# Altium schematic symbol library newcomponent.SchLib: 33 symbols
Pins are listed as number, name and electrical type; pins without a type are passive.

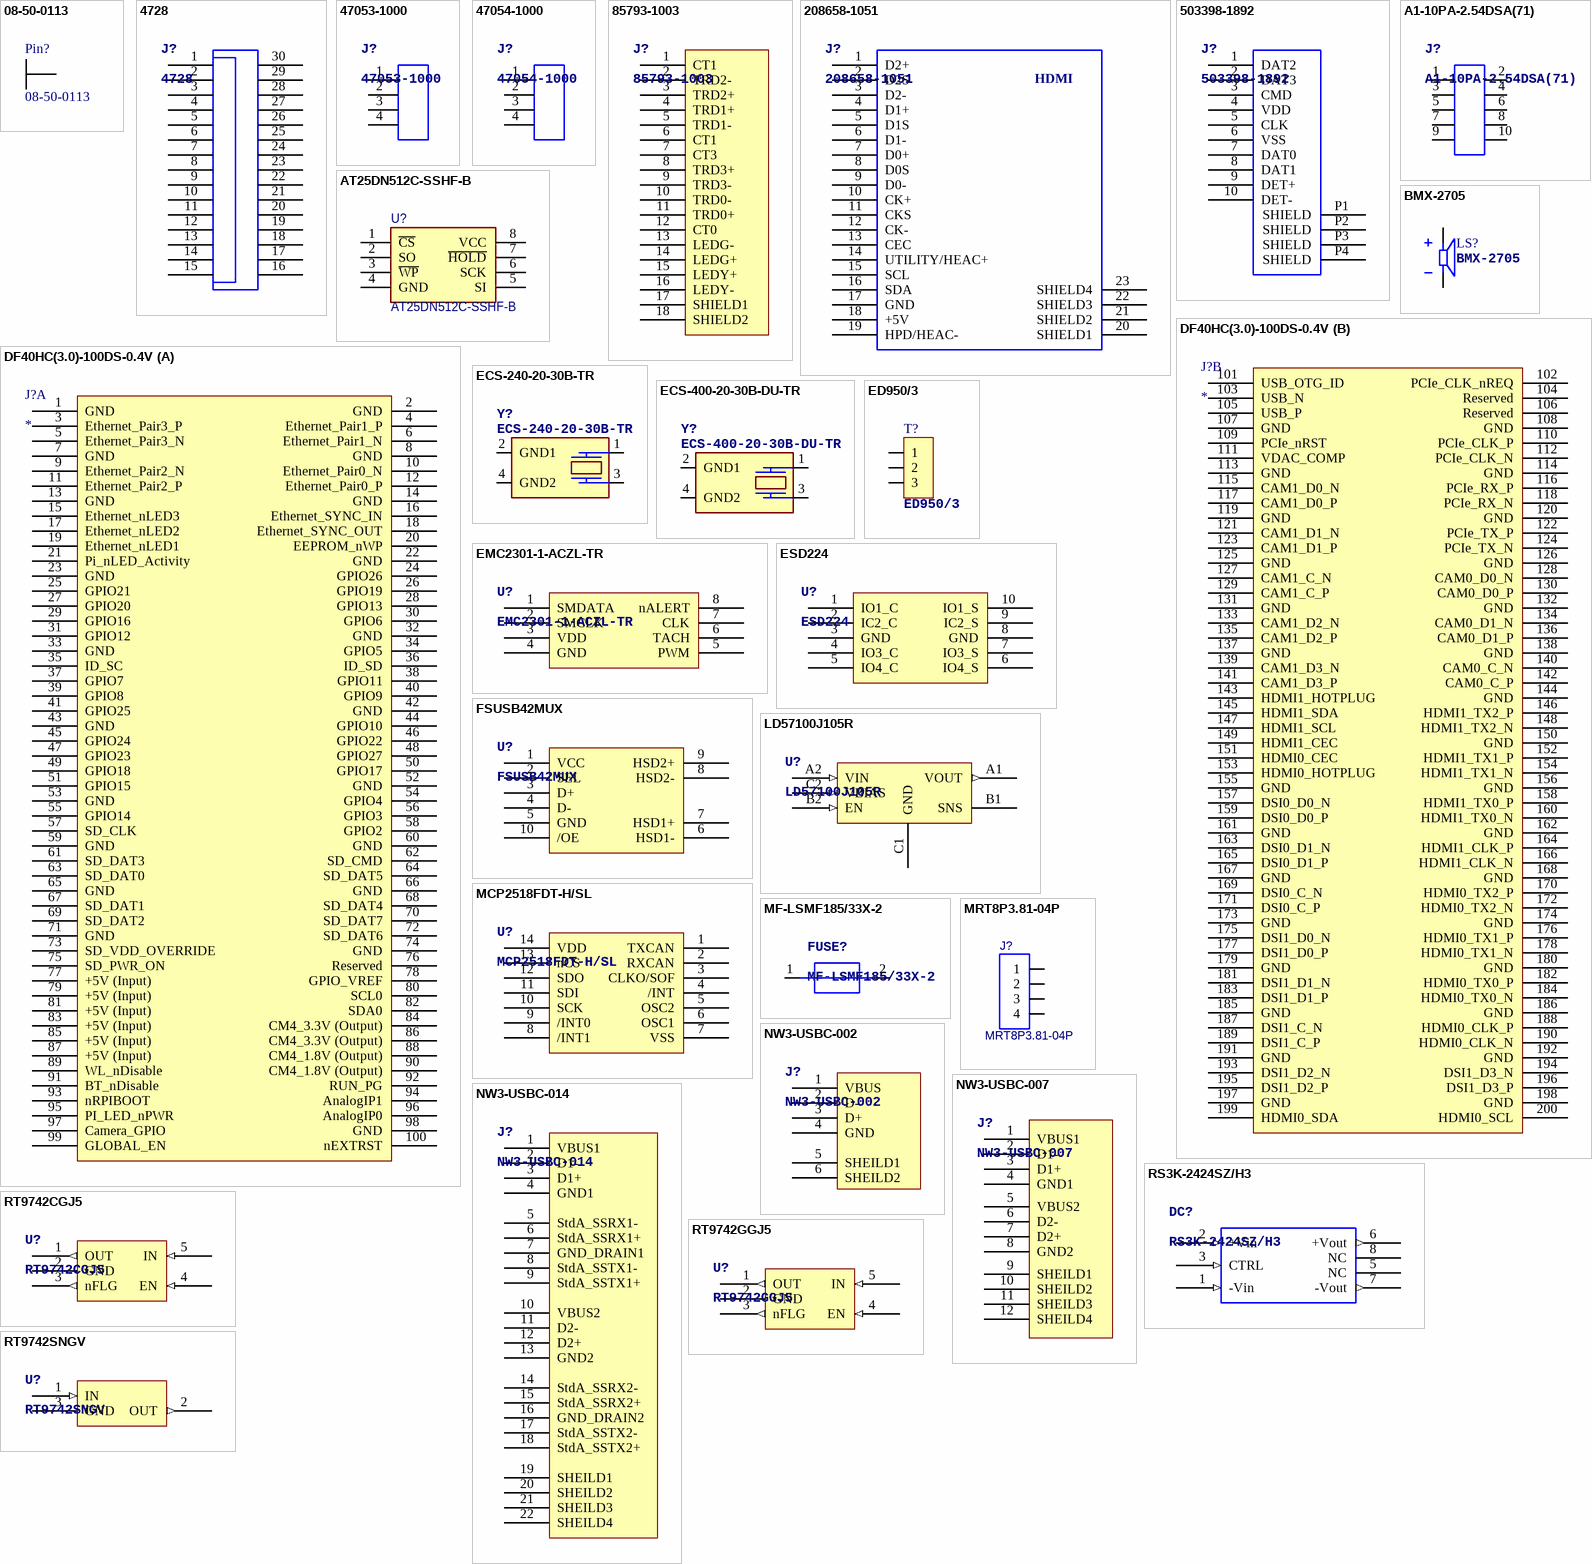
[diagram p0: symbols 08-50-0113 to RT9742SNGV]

## 08-50-0113
designator Pin?  (mechanical)
Headers & Wire Housings KK TERM 22-30G / (Use with 47054-1000); Maker: Molex

## 4728
designator J?
Raspberry Pi Accessories Replacement CSI/DSI Connector for Raspberry Pi - Repair Part; Maker: Adafruit
pins: 1, 2, 3, 4, 5, 6, 7, 8, 9, 10, 11, 12, 13, 14, 15, 16, 17, 18, 19, 20, 21, 22, 23, 24, 25, 26, 27, 28, 29, 30

## 47053-1000
designator J?
KK 254 Vertical Header, with Friction Lock, 4 Circuits, PC Tail Length 3.50mm, Bag; Maker: Molex; Plating: 151ConductorMaterial; Number of Contacts: 4; Gender: Male; Current Rating: 4A; Voltage Rating: 250V; Pitch: 2.54mm; Glow Wire Compliant: Non-compliant
pins: 1, 2, 3, 4

## 47054-1000
designator J?
Headers & Wire Housings KK .100" HSG 04P; PartNo.: 47053-1000; Maker: Molex
pins: 1, 2, 3, 4

## 85793-1003
designator J?
Gigabit Ethernet Connectors 8/8 RA Magnetic Jack Grn/Orange/Grn LED; Maker: Molex
pins: 1 CT1, 2 TRD2-, 3 TRD2+, 4 TRD1+, 5 TRD1-, 6 CT1, 7 CT3, 8 TRD3+, 9 TRD3-, 10 TRD0-, 11 TRD0+, 12 CT0, 13 LEDG-, 14 LEDG+, 15 LEDY+, 16 LEDY-, 17 SHIELD1, 18 SHIELD2

## 208658-1051
designator J?
HDMI 2.1 Receptacle Connector 19 Position Surface Mount, Right Angle; Through Hole; PartNo.: 2086581051; Maker: Molex
pins: 1 D2+, 2 D2S, 3 D2-, 4 D1+, 5 D1S, 6 D1-, 7 D0+, 8 D0S, 9 D0-, 10 CK+, 11 CKS, 12 CK-, 13 CEC, 14 UTILITY/HEAC+, 15 SCL, 16 SDA, 17 GND, 18 +5V, 19 HPD/HEAC-, 20 SHIELD1, 21 SHIELD2, 22 SHIELD3, 23 SHIELD4

## 503398-1892
designator J?
Memory Card Connectors MICRO SD PUSH/PUSH NORMAL 1.28MM 8C; Maker: Molex
pins: 1 DAT2, 2 DAT3, 3 CMD, 4 VDD, 5 CLK, 6 VSS, 7 DAT0, 8 DAT1, 9 DET+, 10 DET-, P1 SHIELD, P2 SHIELD, P3 SHIELD, P4 SHIELD

## A1-10PA-2.54DSA(71)
designator J?
Headers & Wire Housings 10P M PIN HEADER DR STRAIGHT TYPE GOLD; Maker: Hirose
pins: 1, 2, 3, 4, 5, 6, 7, 8, 9, 10

## AT25DN512C-SSHF-B
designator U?
NOR Flash 512 Kbit, 3.0V (2.3V to 3.6V), -40C to 85C, SOIC-N 150mil (Tube), Single, Dual SPI NOR flash; Maker: Renesas / Dialog
footprint SO-08-EIAJ
pins: 1 ~{CS}, 2 SO, 3 ~{WP}, 4 GND, 5 SI, 6 SCK, 7 ~{HOLD}, 8 VCC

## BMX-2705
designator LS?
9 mm, 5 Vdc, 90 dB, SMD Passive, Magnetic Audio Indicator Buzzer; Maker: KANGSEO EST
pins: N, P

## DF40HC(3.0)-100DS-0.4V
designator J?
Board to Board & Mezzanine Connectors 100P 2R 3MM RECPT SMT VERT 0.4MM PITCH; PartNo.: DF40HC(3.0)-100DS-0.4V; Maker: Hirose
part A pins: 1 GND, 2 GND, 3 Ethernet_Pair3_P, 4 Ethernet_Pair1_P, 5 Ethernet_Pair3_N, 6 Ethernet_Pair1_N, 7 GND, 8 GND, 9 Ethernet_Pair2_N, 10 Ethernet_Pair0_N, 11 Ethernet_Pair2_P, 12 Ethernet_Pair0_P, 13 GND, 14 GND, 15 Ethernet_nLED3, 16 Ethernet_SYNC_IN, 17 Ethernet_nLED2, 18 Ethernet_SYNC_OUT, 19 Ethernet_nLED1, 20 EEPROM_nWP, 21 Pi_nLED_Activity, 22 GND, 23 GND, 24 GPIO26, 25 GPIO21, 26 GPIO19, 27 GPIO20, 28 GPIO13, 29 GPIO16, 30 GPIO6, 31 GPIO12, 32 GND, 33 GND, 34 GPIO5, 35 ID_SC, 36 ID_SD, 37 GPIO7, 38 GPIO11, 39 GPIO8, 40 GPIO9, 41 GPIO25, 42 GND, 43 GND, 44 GPIO10, 45 GPIO24, 46 GPIO22, 47 GPIO23, 48 GPIO27, 49 GPIO18, 50 GPIO17, 51 GPIO15, 52 GND, 53 GND, 54 GPIO4, 55 GPIO14, 56 GPIO3, 57 SD_CLK, 58 GPIO2, 59 GND, 60 GND, 61 SD_DAT3, 62 SD_CMD, 63 SD_DAT0, 64 SD_DAT5, 65 GND, 66 GND, 67 SD_DAT1, 68 SD_DAT4, 69 SD_DAT2, 70 SD_DAT7, 71 GND, 72 SD_DAT6, 73 SD_VDD_OVERRIDE, 74 GND, 75 SD_PWR_ON, 76 Reserved, 77 +5V (Input), 78 GPIO_VREF, 79 +5V (Input), 80 SCL0, 81 +5V (Input), 82 SDA0, 83 +5V (Input), 84 CM4_3.3V (Output), 85 +5V (Input), 86 CM4_3.3V (Output), 87 +5V (Input), 88 CM4_1.8V (Output), 89 WL_nDisable, 90 CM4_1.8V (Output), 91 BT_nDisable, 92 RUN_PG, 93 nRPIBOOT, 94 AnalogIP1, 95 PI_LED_nPWR, 96 AnalogIP0, 97 Camera_GPIO, 98 GND, 99 GLOBAL_EN, 100 nEXTRST
part B pins: 101 USB_OTG_ID, 102 PCIe_CLK_nREQ, 103 USB_N, 104 Reserved, 105 USB_P, 106 Reserved, 107 GND, 108 GND, 109 PCIe_nRST, 110 PCIe_CLK_P, 111 VDAC_COMP, 112 PCIe_CLK_N, 113 GND, 114 GND, 115 CAM1_D0_N, 116 PCIe_RX_P, 117 CAM1_D0_P, 118 PCIe_RX_N, 119 GND, 120 GND, 121 CAM1_D1_N, 122 PCIe_TX_P, 123 CAM1_D1_P, 124 PCIe_TX_N, 125 GND, 126 GND, 127 CAM1_C_N, 128 CAM0_D0_N, 129 CAM1_C_P, 130 CAM0_D0_P, 131 GND, 132 GND, 133 CAM1_D2_N, 134 CAM0_D1_N, 135 CAM1_D2_P, 136 CAM0_D1_P, 137 GND, 138 GND, 139 CAM1_D3_N, 140 CAM0_C_N, 141 CAM1_D3_P, 142 CAM0_C_P, 143 HDMI1_HOTPLUG, 144 GND, 145 HDMI1_SDA, 146 HDMI1_TX2_P, 147 HDMI1_SCL, 148 HDMI1_TX2_N, 149 HDMI1_CEC, 150 GND, 151 HDMI0_CEC, 152 HDMI1_TX1_P, 153 HDMI0_HOTPLUG, 154 HDMI1_TX1_N, 155 GND, 156 GND, 157 DSI0_D0_N, 158 HDMI1_TX0_P, 159 DSI0_D0_P, 160 HDMI1_TX0_N, 161 GND, 162 GND, 163 DSI0_D1_N, 164 HDMI1_CLK_P, 165 DSI0_D1_P, 166 HDMI1_CLK_N, 167 GND, 168 GND, 169 DSI0_C_N, 170 HDMI0_TX2_P, 171 DSI0_C_P, 172 HDMI0_TX2_N, 173 GND, 174 GND, 175 DSI1_D0_N, 176 HDMI0_TX1_P, 177 DSI1_D0_P, 178 HDMI0_TX1_N, 179 GND, 180 GND, 181 DSI1_D1_N, 182 HDMI0_TX0_P, 183 DSI1_D1_P, 184 HDMI0_TX0_N, 185 GND, 186 GND, 187 DSI1_C_N, 188 HDMI0_CLK_P, 189 DSI1_C_P, 190 HDMI0_CLK_N, 191 GND, 192 GND, 193 DSI1_D2_N, 194 DSI1_D3_N, 195 DSI1_D2_P, 196 DSI1_D3_P, 197 GND, 198 GND, 199 HDMI0_SDA, 200 HDMI0_SCL

## ECS-240-20-30B-TR
designator Y?
Crystal 24MHz ±30ppm (Tol) ±50ppm (Stability) 20pF FUND 80Ohm 4-Pin Mini-SMD T/R; Maker: ECS
footprint xtal-ECS-120-20-30B-TR
pins: 1 IN/OUT, 2 GND1, 3 OUT/IN, 4 GND2

## ECS-400-20-30B-DU-TR
designator Y?
Crystal 40MHz ±30ppm (Tol) ±100ppm (Stability) 20pF FUND 100Ohm 4-Pin Mini-SMD T/R; Maker: ECS
footprint xtal-ECS-120-20-30B-TR
pins: 1 IN/OUT, 2 GND1, 3 OUT/IN, 4 GND2

## ED950/3
designator T?
TERM BLOCK PLUG 3POS STR 5MM; Maker: OnShore
pins: 1, 2, 3
2 alternate drawings of the same symbol

## EMC2301-1-ACZL-TR
designator U?
Board Mount Temperature Sensors Single RPB-Based PWM Fan Speed CNTRL; Maker: Microchip
pins: 1 SMDATA, 2 SMCLK, 3 VDD, 4 GND, 5 PWM, 6 TACH, 7 CLK, 8 nALERT

## ESD224
designator U?
ESD Suppressors / TVS Diodes Quad 0.5-pF, 3.6-V, 12-kV ESD protection diode for USB &amp; HDMI 10-USON -40 to 125; Maker: TI
pins: 1 IO1_C, 2 IC2_C, 3 GND, 4 IO3_C, 5 IO4_C, 6 IO4_S, 7 IO3_S, 8 GND, 9 IC2_S, 10 IO1_S

## FSUSB42MUX
designator U?
USB Switch ICs Low Power, Two-Port USB 2.0 (480Mbps); Maker: ONSEMI
pins: 1 VCC, 2 SEL, 3 D+, 4 D-, 5 GND, 6 HSD1-, 7 HSD1+, 8 HSD2-, 9 HSD2+, 10 /OE

## LD57100J105R
designator U?
LDO Voltage Regulators 3V~5.5V to 1.05V 1A ultra low-dropout LDO bias; Maker: STMicroelectronics
pins: A1 VOUT (out), A2 VIN (in), B1 SNS, B2 EN (in), C1 GND, C2 VBIAS (in)

## MCP2518FDT-H/SL
designator U?
CAN Interface IC Stand-alone Low Power CAN FD Controller s/SPI Interface Grade 0; Maker: MIcrochip
pins: 1 TXCAN, 2 RXCAN, 3 CLKO/SOF, 4 /INT, 5 OSC2, 6 OSC1, 7 VSS, 8 /INT1, 9 /INT0, 10 SCK, 11 SDI, 12 SDO, 13 nCS, 14 VDD

## MF-LSMF185/33X-2
designator FUSE?
Resettable Fuses - PPTC PTC RESETTABLE 1.85A 33V SMD 2920; Maker: Bourns
pins: 1, 2

## MRT8P3.81-04P
designator J?
TERM BLOCK PLUG 4POS STR 3.81mm(MRT9P3.81SQ-04P need); Maker: STELVIO
pins: 1, 2, 3, 4

## NW3-USBC-002
designator J?
USB 2.0 A/F Connector, Right angle; Maker: NW3
pins: 1 VBUS, 2 D-, 3 D+, 4 GND, 5 SHEILD1, 6 SHEILD2

## NW3-USBC-007
designator J?
USB 2.0 A/F 2 stack Connector, Right angle; Maker: NW3
pins: 1 VBUS1, 2 D1-, 3 D1+, 4 GND1, 5 VBUS2, 6 D2-, 7 D2+, 8 GND2, 9 SHEILD1, 10 SHEILD2, 11 SHEILD3, 12 SHEILD4

## NW3-USBC-014
designator J?
USB 3.0 A/F 2 stack Connector, Right angle; Maker: NW3
pins: 1 VBUS1, 2 D1-, 3 D1+, 4 GND1, 5 StdA_SSRX1-, 6 StdA_SSRX1+, 7 GND_DRAIN1, 8 StdA_SSTX1-, 9 StdA_SSTX1+, 10 VBUS2, 11 D2-, 12 D2+, 13 GND2, 14 StdA_SSRX2-, 15 StdA_SSRX2+, 16 GND_DRAIN2, 17 StdA_SSTX2-, 18 StdA_SSTX2+, 19 SHEILD1, 20 SHEILD2, 21 SHEILD3, 22 SHEILD4

## RS3K-2424SZ/H3
designator DC?
Isolated DC/DC Converters - Through Hole 3W 9-36Vin 24Vout 125mA; Maker: RECOM
pins: 1 -Vin (in), 2 +Vin (in), 3 CTRL (in), 5 NC, 6 +Vout (out), 7 -Vout (out), 8 NC

## RT9742CGJ5
designator U?
Power Switch ICs - Power Distribution 70mohm, 2A High-Side Power Switches with flag; Maker: Richtek
pins: 1 OUT (out), 2 GND, 3 nFLG (out), 4 EN (in), 5 IN (in)

## RT9742GGJ5
designator U?
Power Switch ICs - Power Distribution 70mohm, 1A High-Side Power Switches with flag; Maker: Richtek
pins: 1 OUT (out), 2 GND, 3 nFLG (out), 4 EN (in), 5 IN (in)

## RT9742SNGV
designator U?
Power Switch ICs - Power Distribution 70mohm, 0.5A High-Side Power Switches, Current Limiter; Maker: Richtek
pins: 1 IN (in), 2 OUT (out), 3 GND

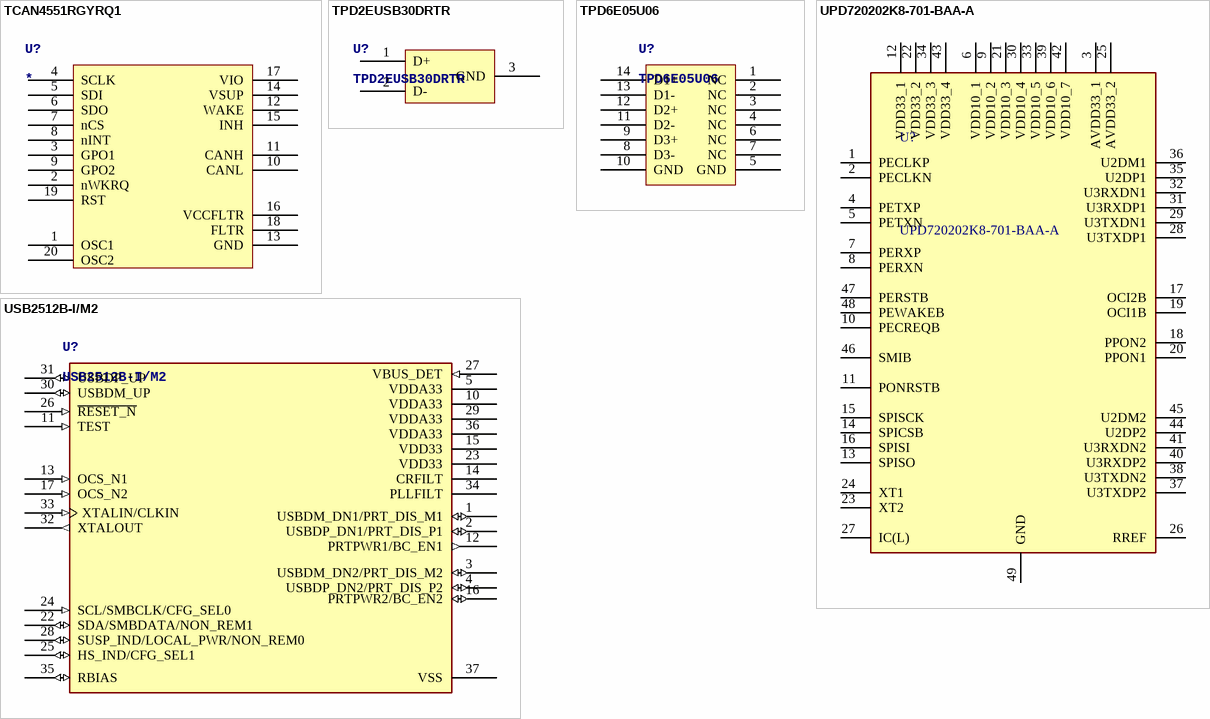
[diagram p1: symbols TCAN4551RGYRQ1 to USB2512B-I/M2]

## TCAN4551RGYRQ1
designator U?
CAN Interface IC Automotive control area network flexible data rate (CAN FD) controller with integrated transceiver 20-VQFN -40 to 125; PartNo.: TCAN4551RGYRQ1; Maker: TI
pins: 1 OSC1, 2 nWKRQ, 3 GPO1, 4 SCLK, 5 SDI, 6 SDO, 7 nCS, 8 nINT, 9 GPO2, 10 CANL, 11 CANH, 12 WAKE, 13 GND, 14 VSUP, 15 INH, 16 VCCFLTR, 17 VIO, 18 FLTR, 19 RST, 20 OSC2

## TPD2EUSB30DRTR
designator U?
ESD Suppressors / TVS Diodes 2Ch ESD Solution; PartNo.: Package; Maker: TI
pins: 1 D+, 2 D-, 3 GND

## TPD6E05U06
designator U?
ESD Suppressors / TVS Diodes 6-CH lo cap IEC ESD protect diodes; Maker: TI
pins: 1 NC, 2 NC, 3 NC, 4 NC, 5 GND, 6 NC, 7 NC, 8 D3-, 9 D3+, 10 GND, 11 D2-, 12 D2+, 13 D1-, 14 D1+

## UPD720202K8-701-BAA-A
designator U?
PD720202 is a USB host controller LSI compatible with the USB 3.0 and xHCI (eXtensible Host Controller Interface) 1.0 specifications. The system bus is compatible with the PCIe Gen2 specification. The controller provides two USB ports with LS (Low-Speed) / FS (Full-Speed) / HS (High-Speed) / SS (SuperSpeed) support.PD720202 comes in a 48-pin QFN package and has the following improvements over previous products.	Reduced power consumption in low-power mode to 4.5mW, a reduction of 90% compared with Renesas; Manufacturer_Name: Renesas Electronics; Geometry.Height: 0.9mm
footprint QFN50P700X700X90-49N-D
pins: 1 PECLKP, 2 PECLKN, 3 AVDD33_1, 4 PETXP, 5 PETXN, 6 VDD10_1, 7 PERXP, 8 PERXN, 9 VDD10_2, 10 PECREQB, 11 PONRSTB, 12 VDD33_1, 13 SPISO, 14 SPICSB, 15 SPISCK, 16 SPISI, 17 OCI2B, 18 PPON2, 19 OCI1B, 20 PPON1, 21 VDD10_3, 22 VDD33_2, 23 XT2, 24 XT1, 25 AVDD33_2, 26 RREF, 27 IC(L), 28 U3TXDP1, 29 U3TXDN1, 30 VDD10_4, 31 U3RXDP1, 32 U3RXDN1, 33 VDD10_5, 34 VDD33_3, 35 U2DP1, 36 U2DM1, 37 U3TXDP2, 38 U3TXDN2, 39 VDD10_6, 40 U3RXDP2, 41 U3RXDN2, 42 VDD10_7, 43 VDD33_4, 44 U2DP2, 45 U2DM2, 46 SMIB, 47 PERSTB, 48 PEWAKEB, 49 GND

## USB2512B-I/M2
designator U?
USB Interface IC 2-Port USB 2.0 Hi-Speed Hub Cont; Maker: Microchip
pins: 1 USBDM_DN1/PRT_DIS_M1 (io), 2 USBDP_DN1/PRT_DIS_P1 (io), 3 USBDM_DN2/PRT_DIS_M2 (io), 4 USBDP_DN2/PRT_DIS_P2 (io), 5 VDDA33 (power), 10 VDDA33 (power), 11 TEST (in), 12 PRTPWR1/BC_EN1 (out), 13 OCS_N1 (in), 14 CRFILT (power), 15 VDD33 (power), 16 PRTPWR2/BC_EN2 (io), 17 OCS_N2 (in), 22 SDA/SMBDATA/NON_REM1 (io), 23 VDD33 (power), 24 SCL/SMBCLK/CFG_SEL0 (in), 25 HS_IND/CFG_SEL1 (io), 26 ~{RESET_N} (in), 27 VBUS_DET (in), 28 SUSP_IND/LOCAL_PWR/NON_REM0 (io), 29 VDDA33 (power), 30 USBDM_UP (io), 31 USBDP_UP (io), 32 XTALOUT (out), 33 XTALIN/CLKIN (in), 34 PLLFILT (power), 35 RBIAS (io), 36 VDDA33 (power), 37 VSS (power)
